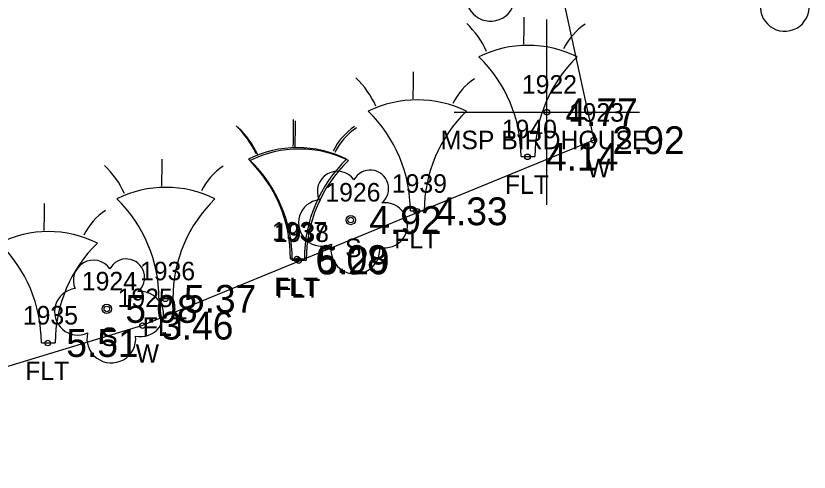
# Model space of a CAD drawing. Extents: x 2608598 to 2610682, y 641451 to 643526.
# Drawn here: x 2609231.28 to 2609274.09, y 642873.67 to 642898.29 of the extents above; entities that cross this region are included whole.
import ezdxf

# ---------------------------------------------------------------- set-up
doc = ezdxf.new("R2010")
doc.units = 0
for name, color, linetype in [('RD_EX_BldgApp', 7, 'Continuous'), ('RD_EX_BldgApp_txCode', 7, 'Continuous'), ('RD_EX_Misc', 7, 'Continuous'), ('RD_EX_Misc_txCode', 7, 'Continuous'), ('RD_EX_TX_BldgApp_ELEV', 7, 'Continuous'), ('RD_EX_TX_Misc_ELEV', 7, 'Continuous'), ('RD_EX_TX_VEG_ELEV', 7, 'Continuous'), ('RD_EX_VEG', 7, 'Continuous'), ('RD_EX_VEG_txCode', 7, 'Continuous'), ('RD_SMD_Locator', 7, 'Continuous')]:
    doc.layers.add(name, color=color, linetype=linetype)

msp = doc.modelspace()

# ---------------------------------------------------------------- linework, layer by layer
at = {"layer": 'RD_EX_BldgApp'}
for p, q in [((2609258.543, 642890.703), (2609259.293, 642890.703)), ((2609252.57, 642887.762), (2609253.32, 642887.762)), ((2609246.102, 642885.182), (2609246.852, 642885.182)), ((2609246.199, 642885.107), (2609246.949, 642885.107)), ((2609239.002, 642883.038), (2609239.752, 642883.038)), ((2609232.655, 642880.651), (2609233.405, 642880.651))]:
    msp.add_line(p, q, dxfattribs=at)
msp.add_lwpolyline([(2609259.329, 642906.089), (2609262.471, 642891.581), (2609238.117, 642881.572), (2609215.937, 642874.826), (2609203.404, 642873.665)], dxfattribs=at)
for centre, radius, start, end in [((2609220.837, 642898.041), 37.876, 358.0671, 0.2715), ((2609252.226, 642894.346), 4.895, 24.3279, 46.2665), ((2609263.807, 642895.096), 3.283, 123.2906, 154.4886), ((2609258.918, 642890.703), 5.997, 63.7794, 116.2206), ((2609251.043, 642890.703), 7.5, 0, 45.8366), ((2609266.793, 642890.703), 7.5, 134.1634, 180), ((2609214.863, 642895.1), 37.876, 358.0671, 0.2715), ((2609246.252, 642891.404), 4.895, 24.3279, 46.2665), ((2609257.833, 642892.155), 3.283, 123.2906, 154.4886), ((2609252.945, 642887.762), 5.997, 63.7794, 116.2206), ((2609245.07, 642887.762), 7.5, 0, 45.8366), ((2609260.82, 642887.762), 7.5, 134.1634, 180), ((2609208.395, 642892.52), 37.876, 358.0671, 0.2715), ((2609208.493, 642892.445), 37.876, 358.0671, 0.2715), ((2609239.784, 642888.825), 4.895, 24.3279, 46.2665), ((2609239.882, 642888.75), 4.895, 24.3279, 46.2665), ((2609251.365, 642889.575), 3.283, 123.2906, 154.4886), ((2609251.462, 642889.5), 3.283, 123.2906, 154.4886), ((2609246.477, 642885.182), 5.997, 63.7794, 116.2206), ((2609246.574, 642885.107), 5.997, 63.7794, 116.2206), ((2609201.296, 642890.376), 37.876, 358.0671, 0.2715), ((2609238.602, 642885.182), 7.5, 0, 45.8366), ((2609238.699, 642885.107), 7.5, 0, 45.8366), ((2609254.352, 642885.182), 7.5, 134.1634, 180), ((2609254.449, 642885.107), 7.5, 134.1634, 180), ((2609232.685, 642886.681), 4.895, 24.3279, 46.2665), ((2609244.266, 642887.431), 3.283, 123.2906, 154.4886), ((2609239.377, 642883.038), 5.997, 63.7794, 116.2206), ((2609231.502, 642883.038), 7.5, 0, 45.8366), ((2609247.252, 642883.038), 7.5, 134.1634, 180), ((2609194.949, 642887.989), 37.876, 358.0671, 0.2715), ((2609237.918, 642885.044), 3.283, 123.2906, 154.4886), ((2609233.03, 642880.651), 5.997, 63.7794, 116.2206), ((2609225.155, 642880.651), 7.5, 0, 45.8366), ((2609240.905, 642880.651), 7.5, 134.1634, 180)]:
    msp.add_arc(centre, radius, start, end, dxfattribs=at)
at = {"layer": 'RD_EX_Misc'}
for p, q in [((2609259.937, 642888.094), (2609259.937, 642898.094)), ((2609254.937, 642893.094), (2609264.937, 642893.094))]:
    msp.add_line(p, q, dxfattribs=at)
at = {"layer": 'RD_EX_VEG'}
for centre in [(2609249.354, 642887.271), (2609236.187, 642882.474)]:
    msp.add_circle(centre, 0.25, dxfattribs=at)
for centre, radius, start, end in [((2609256.895, 642899.323), 1.318, 166.8827, 5.7589), ((2609272.774, 642898.782), 1.318, 166.8827, 5.7589), ((2609250.4, 642888.973), 0.995, 308.7626, 152.0467), ((2609248.633, 642888.818), 1.084, 34.9763, 204.756), ((2609247.791, 642887.115), 1.257, 96.4518, 294.734), ((2609251.194, 642886.991), 1.218, 256.5667, 98.1046), ((2609249.6, 642885.674), 1.318, 166.8827, 5.7589), ((2609235.466, 642884.022), 1.084, 34.9763, 204.756), ((2609237.232, 642884.176), 0.995, 308.7626, 152.0467), ((2609234.623, 642882.319), 1.257, 96.4518, 294.734), ((2609238.027, 642882.195), 1.218, 256.5667, 98.1046), ((2609236.433, 642880.878), 1.318, 166.8827, 5.7589)]:
    msp.add_arc(centre, radius, start, end, dxfattribs=at)
at = {"layer": 'RD_SMD_Locator'}
for centre in [(2609259.937, 642893.094), (2609262.471, 642891.581), (2609258.891, 642890.685), (2609252.917, 642887.744), (2609249.354, 642887.271), (2609246.449, 642885.164), (2609246.546, 642885.089), (2609239.35, 642883.02), (2609236.187, 642882.474), (2609238.117, 642881.572), (2609233.002, 642880.633)]:
    msp.add_circle(centre, 0.15, dxfattribs=at)

# ---------------------------------------------------------------- texts
at = {"layer": 'RD_EX_BldgApp_txCode'}
for s, p in [('1940', (2609257.505, 642891.685)), ('1939', (2609251.57, 642888.744)), ('FLT', (2609257.67, 642888.685)), ('1937', (2609245.102, 642886.164)), ('1938', (2609245.2, 642886.089)), ('FLT', (2609251.696, 642885.744)), ('1936', (2609237.98, 642884.02)), ('FLT', (2609245.228, 642883.164)), ('FLT', (2609245.326, 642883.089)), ('1935', (2609231.656, 642881.633)), ('FLT', (2609238.129, 642881.02)), ('FLT', (2609231.782, 642878.633))]:
    msp.add_text(s, height=1, dxfattribs=at).set_placement(p)
at = {"layer": 'RD_EX_Misc_txCode'}
for s, p in [('1922', (2609258.59, 642894.094)), ('1923', (2609261.124, 642892.581)), ('MSP BIRDHOUSE', (2609254.209, 642891.094)), ('W', (2609262.101, 642889.581)), ('1925', (2609236.771, 642882.572)), ('W', (2609237.747, 642879.572))]:
    msp.add_text(s, height=1, dxfattribs=at).set_placement(p)
at = {"layer": 'RD_EX_TX_BldgApp_ELEV'}
for s, p in [('4.14', (2609259.891, 642889.935)), ('4.33', (2609253.917, 642886.994)), ('6.08', (2609247.449, 642884.414)), ('5.29', (2609247.546, 642884.339)), ('5.37', (2609240.35, 642882.27)), ('5.51', (2609234.002, 642879.883))]:
    msp.add_text(s, height=1.5, dxfattribs=at).set_placement(p)
at = {"layer": 'RD_EX_TX_Misc_ELEV'}
for s, p in [('4.77', (2609260.937, 642892.344)), ('2.92', (2609263.471, 642890.831)), ('3.46', (2609239.117, 642880.822))]:
    msp.add_text(s, height=1.5, dxfattribs=at).set_placement(p)
at = {"layer": 'RD_EX_TX_VEG_ELEV'}
for s, p in [('4.92', (2609250.354, 642886.521)), ('5.08', (2609237.187, 642881.724))]:
    msp.add_text(s, height=1.5, dxfattribs=at).set_placement(p)
at = {"layer": 'RD_EX_VEG_txCode'}
for s, p in [('1926', (2609247.984, 642888.271)), ('S', (2609249.047, 642885.271)), ('1924', (2609234.841, 642883.474)), ('S', (2609235.88, 642880.474))]:
    msp.add_text(s, height=1, dxfattribs=at).set_placement(p)

doc.saveas('drawing.dxf')
